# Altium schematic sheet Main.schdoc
size 316 x 210 mm
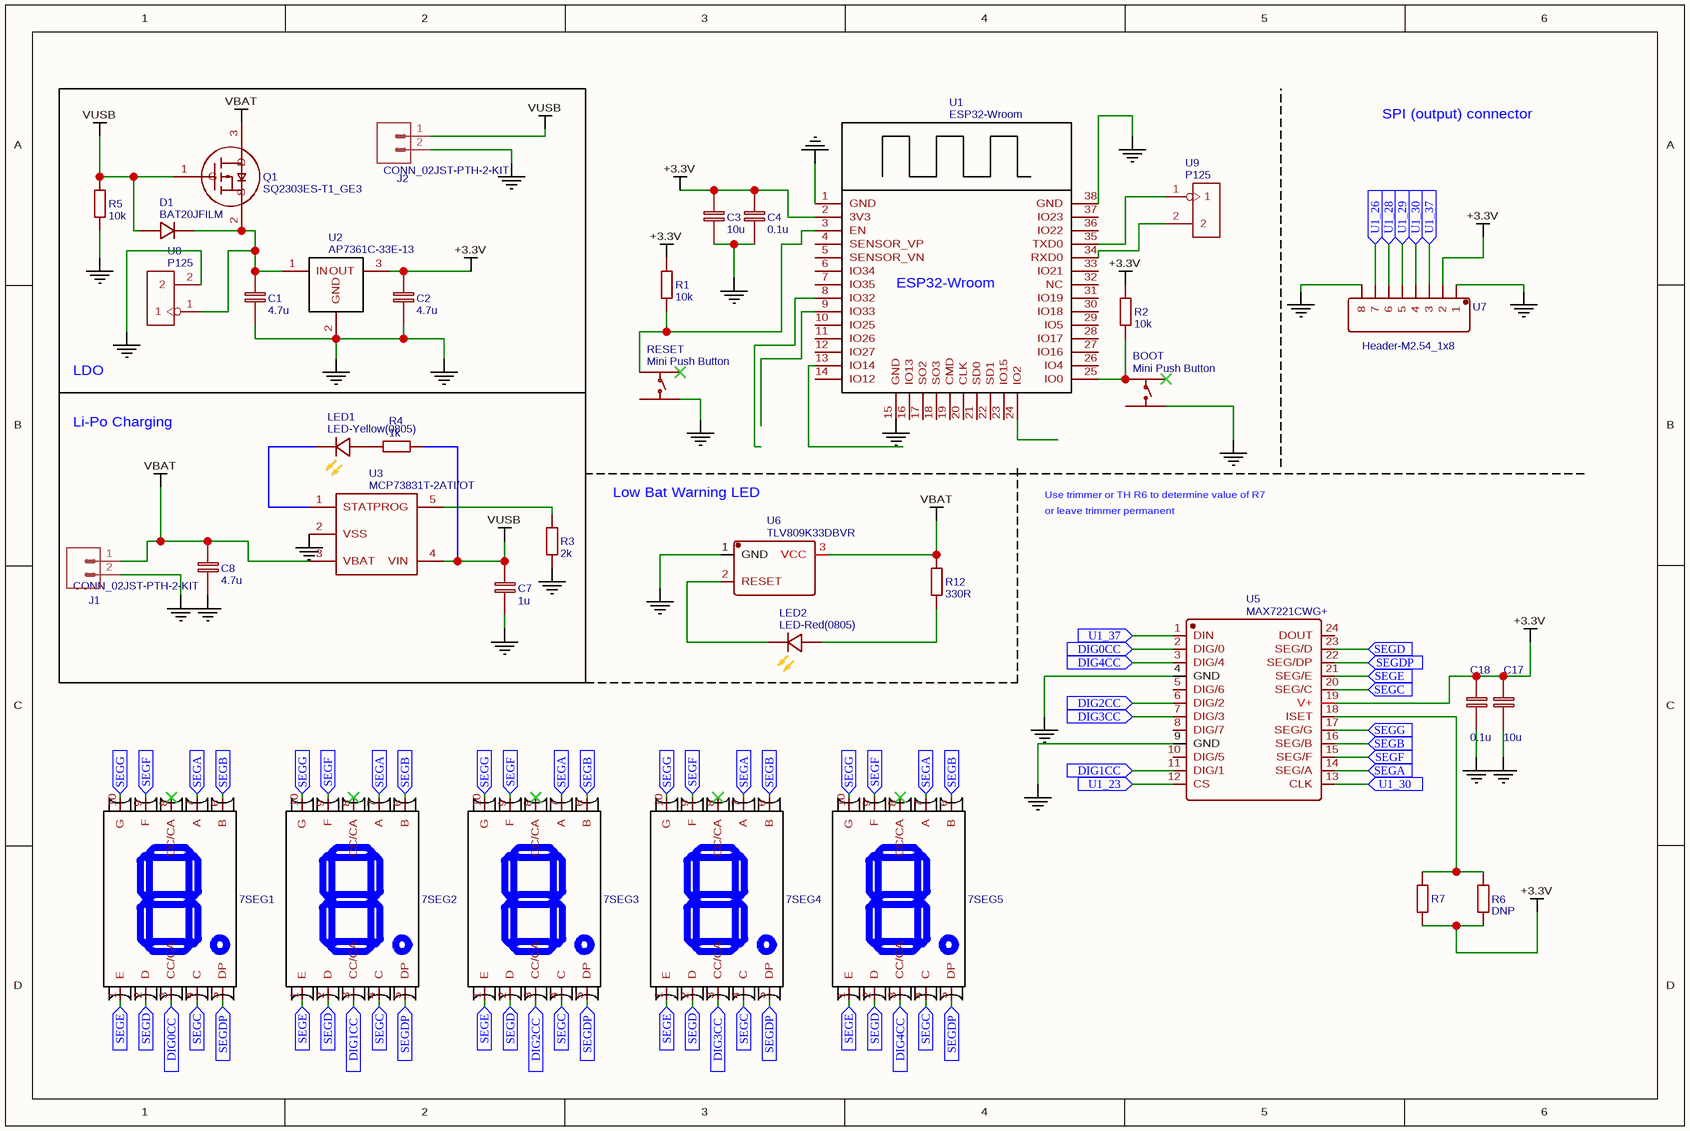
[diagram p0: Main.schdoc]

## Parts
7SEG1  VDMX10X  [VDMX10X LED SEGMENT SMD 10MM]  (value not drawn)
7SEG2  VDMX10X  [VDMX10X LED SEGMENT SMD 10MM]  (value not drawn)
7SEG3  VDMX10X  [VDMX10X LED SEGMENT SMD 10MM]  (value not drawn)
7SEG4  VDMX10X  [VDMX10X LED SEGMENT SMD 10MM]  (value not drawn)
7SEG5  VDMX10X  [VDMX10X LED SEGMENT SMD 10MM]  (value not drawn)
BOOT  Mini Push Button  [SMD-BUTTON]
C1  4.7u  [0805]
C2  4.7u  [0805]
C3  10u  [0805]
C4  0.1u  [0805]
C7  1u  [0805]
C8  4.7u  [0805]
C17  10u  [0805]
C18  0.1u  [0805]
D1  BAT20JFILM  [SOD-323]
J1  CONN_02JST-PTH-2-KIT  [JST-2-PTH-KIT]
J2  CONN_02JST-PTH-2-KIT  [JST-2-PTH-KIT]
LED1  LED-Yellow(0805)  [LED-0805]
LED2  LED-Red(0805)  [LED-0805]
Q1  SQ2303ES-T1_GE3  [SOT-23(SOT-23-3)]
R1  10k  [0805]
R2  10k  [0805]
R3  2k  [0805]
R4  1k  [0805]
R5  10k  [0805]
R6  DNP  [AXIAL-0.4]
R7  ???K  [0805]  (value not drawn)
R12  330R  [0805]
RESET  Mini Push Button  [SMD-BUTTON]
U1  ESP32-Wroom  [ESP32_WROOM_FOOTPRINT]
U2  AP7361C-33E-13  [SOT223-4]
U3  MCP73831T-2ATI/OT  [SOT-23-5]
U5  MAX7221CWG+  [SOIC-24]
U6  TLV809K33DBVR  [SOT-23-3]
U7  Header-M2.54_1x8  [210S-1X8P]
U8  P125  [H2-2.54]
U9  P125  [H2-2.54]

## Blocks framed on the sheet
LDO: C1 C2 D1 J2 Q1 R5 U2 U8

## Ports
DIG0CC, DIG1CC, DIG2CC, DIG3CC, DIG4CC, SEGA, SEGB, SEGC, SEGD, SEGDP, SEGE, SEGF, SEGG, U1_23, U1_26, U1_28, U1_29, U1_30, U1_37

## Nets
+3.3V: C2.1 C3.1 C4.1 C17.1 C18.1 U1.2(3V3) U2.3(OUT) U5.19(V+) U7.2
GND: BOOT.2 C1.2 C2.2 C3.2 C4.2 C7.2 C8.2 C17.2 C18.2 J1.2 J2.2 RESET.2 U1.1(GND) U1.15(GND) U1.38(GND) U2.2(GND) U3.2(VSS) U5.4(GND) U5.9(GND) U6.1(GND) U7.1 U7.8 U8.2
VBAT: C8.1 J1.1 Q1.3(D) U3.3(VBAT) U6.3(VCC)
VUSB: C7.1 D1.1(A) J2.1 Q1.1(G) U3.4(VIN)
DIG0CC: 7SEG1.3(CC/CA) U5.2(DIG/0) ; port DIG0CC
DIG1CC: 7SEG2.3(CC/CA) U5.11(DIG/1) ; port DIG1CC
DIG2CC: 7SEG3.3(CC/CA) U5.6(DIG/2) ; port DIG2CC
DIG3CC: 7SEG4.3(CC/CA) U5.7(DIG/3) ; port DIG3CC
DIG4CC: 7SEG5.3(CC/CA) U5.3(DIG/4) ; port DIG4CC
SEGA: 7SEG1.7(A) 7SEG2.7(A) 7SEG3.7(A) 7SEG4.7(A) 7SEG5.7(A) U5.14(SEG/A) ; port SEGA
SEGB: 7SEG1.6(B) 7SEG2.6(B) 7SEG3.6(B) 7SEG4.6(B) 7SEG5.6(B) U5.16(SEG/B) ; port SEGB
SEGC: 7SEG1.4(C) 7SEG2.4(C) 7SEG3.4(C) 7SEG4.4(C) 7SEG5.4(C) U5.20(SEG/C) ; port SEGC
SEGD: 7SEG1.2(D) 7SEG2.2(D) 7SEG3.2(D) 7SEG4.2(D) 7SEG5.2(D) U5.23(SEG/D) ; port SEGD
SEGDP: 7SEG1.5(DP) 7SEG2.5(DP) 7SEG3.5(DP) 7SEG4.5(DP) 7SEG5.5(DP) U5.22(SEG/DP) ; port SEGDP
SEGE: 7SEG1.1(E) 7SEG2.1(E) 7SEG3.1(E) 7SEG4.1(E) 7SEG5.1(E) U5.21(SEG/E) ; port SEGE
SEGF: 7SEG1.9(F) 7SEG2.9(F) 7SEG3.9(F) 7SEG4.9(F) 7SEG5.9(F) U5.15(SEG/F) ; port SEGF
SEGG: 7SEG1.10(G) 7SEG2.10(G) 7SEG3.10(G) 7SEG4.10(G) 7SEG5.10(G) U5.17(SEG/G) ; port SEGG
U1_23: U5.12(CS) ; port U1_23
U1_26: U7.7 ; port U1_26
U1_28: U7.6 ; port U1_28
U1_29: U7.5 ; port U1_29
U1_30: U5.13(CLK) U7.4 ; port U1_30
U1_37: U5.1(DIN) U7.3 ; port U1_37
NetBOOT_1: BOOT.1 U1.25(IO0)
NetC1_1: C1.1 D1.2(K) Q1.2(S) U2.1(IN) U8.1
NetLED1_2: LED1.2(-) U3.1(STAT)
NetLED2_2: LED2.2(-) U6.2(RESET)
NetRESET_1: RESET.1 U1.3(EN)
NetU1_34: U1.34(RXD0) U9.2
NetU1_35: U1.35(TXD0) U9.1

Not connected (* = marked no-connect by the designer): 7SEG1 8(CC/CA)*; 7SEG2 8(CC/CA)*; 7SEG3 8(CC/CA)*; 7SEG4 8(CC/CA)*; 7SEG5 8(CC/CA)*; LED1 1(+); LED2 1(+); R1 1 2; R2 1 2; R3 1 2; R4 1 2; R5 1 2; R6 1 2; R7 1 2; R12 1 2; U1 4(SENSOR_VP) 5(SENSOR_VN) 6(IO34) 7(IO35) 8(IO32) 9(IO33) 10(IO25) 11(IO26) 12(IO27) 13(IO14) 14(IO12) 16(IO13) 17(SO2) 18(SO3) 19(CMD) 20(CLK) 21(SD0) 22(SD1) 23(IO15) 24(IO2) 26(IO4) 27(IO16) 28(IO17) 29(IO5) 30(IO18) 31(IO19) 32(NC) 33(IO21) 36(IO22) 37(IO23); U3 5(PROG); U5 5(DIG/6) 8(DIG/7) 10(DIG/5) 18(ISET) 24(DOUT)

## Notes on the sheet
- SPI (output) connector
- Li-Po Charging
- Low Bat Warning LED
- Use trimmer or TH R6 to determine value of R7
- or leave trimmer permanent
- Labels drawn without touching a wire or pin: +3.3V, GND

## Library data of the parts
7SEG1-7SEG5 = VDMX10X: BOM_Manufacturer Part: Vishay Semiconductors; Contributor: jousis
BOOT RESET = Mini Push Button: BOM_Manufacturer: SparkFun Electronics; BOM_Manufacturer Part: COM-08720; Contributor: markneilpita.26
C1 C2 C8 = 4.7u: nameAlias: Value(F)
C3 C17 = 10u: nameAlias: Value(F)
C4 C18 = 0.1u: nameAlias: Value(F)
C7 = 1u: nameAlias: Value(F)
D1 = BAT20JFILM: BOM_Manufacturer: STMicroelectronics; Contributor: LCSC
J1 J2 = CONN_02JST-PTH-2-KIT: Contributor: Elvedin Rosic
LED1 = LED-Yellow(0805): BOM_Manufacturer: Hubei KENTO Elec; BOM_Manufacturer Part: 17-21SUYC/TR8
LED2 = LED-Red(0805): BOM_Manufacturer: Hubei KENTO Elec; BOM_Manufacturer Part: 17-21SUYC/TR8
Q1 = SQ2303ES-T1_GE3: BOM_Manufacturer: VISHAY; Contributor: LCSC
R1 R2 R5 = 10k: nameAlias: Value(Ω)
R3 = 2k: nameAlias: Value(Ω)
R4 = 1k: nameAlias: Value(Ω)
R6 = DNP: nameAlias: Value(Ω)
R7 = ???K: nameAlias: Value(Ω)
R12 = 330R: nameAlias: Value(Ω)
U1 = ESP32-Wroom: Contributor: cunt123
U2 = AP7361C-33E-13: Contributor: luizazv
U3 = MCP73831T-2ATI/OT: BOM_Manufacturer: MICROCHIP
U6 = TLV809K33DBVR: BOM_Manufacturer: TI
U7 = Header-M2.54_1x8: BOM_Manufacturer: Ckmtw; BOM_Manufacturer Part: 210S-1*8P L=11.6MMGold-plated black; Contributor: LCSC
U8 U9 = P125: BOM_Manufacturer Part: P125-1102A0BS116A2; description: DIP Blue Male Header VERT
